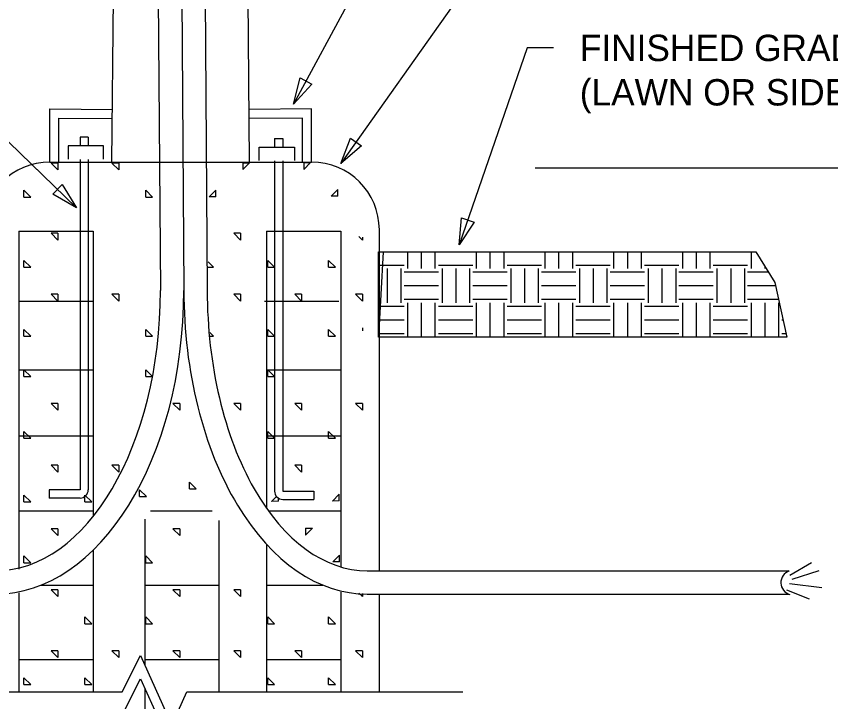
# Model space of a CAD drawing. Extents: x 10112 to 10168, y 10050 to 10179.
# Drawn here: x 10136.31 to 10156.9, y 10084.18 to 10101.49 of the extents above; entities that cross this region are included whole.
import ezdxf

# ---------------------------------------------------------------- set-up
doc = ezdxf.new("R2010")
doc.units = 0
for name, color, linetype in [('G-ANNO-TEXT', 7, 'Continuous'), ('G-DETL-LINE', 7, 'Continuous'), ('G-DETL-OTLN', 7, 'Continuous'), ('G-DETL-PATT', 7, 'Continuous')]:
    doc.layers.add(name, color=color, linetype=linetype)

msp = doc.modelspace()

# ---------------------------------------------------------------- linework, layer by layer
at = {"layer": 'G-ANNO-TEXT'}
for p, q in [((10148.104, 10108.141), (10143.31, 10099.275)), ((10129.887, 10104.328), (10137.827, 10096.658)), ((10148.282, 10103.102), (10144.508, 10097.776)), ((10149.219, 10100.696), (10147.504, 10095.721)), ((10149.886, 10100.696), (10149.219, 10100.696)), ((10149.421, 10097.663), (10167.894, 10097.663))]:
    msp.add_line(p, q, dxfattribs=at)
for points in [[(10143.774, 10099.782), (10143.31, 10099.275), (10143.48, 10099.941)], [(10145.03, 10098.224), (10144.508, 10097.776), (10144.758, 10098.417)], [(10137.464, 10097.241), (10137.827, 10096.658), (10137.232, 10097.001)], [(10147.879, 10096.297), (10147.504, 10095.721), (10147.564, 10096.406)]]:
    msp.add_lwpolyline(points, close=True, dxfattribs=at)
at = {"layer": 'G-DETL-LINE'}
for p, q in [((10137.384, 10097.812), (10137.384, 10098.923)), ((10137.384, 10098.923), (10138.734, 10098.916)), ((10143.545, 10098.923), (10142.195, 10098.916)), ((10143.545, 10097.812), (10143.545, 10098.923)), ((10137.916, 10098.443), (10137.916, 10098.219)), ((10138.124, 10098.443), (10137.916, 10098.443)), ((10138.124, 10098.443), (10138.124, 10098.219)), ((10142.835, 10098.408), (10143.043, 10098.408)), ((10142.835, 10098.408), (10142.835, 10098.185)), ((10143.043, 10098.408), (10143.043, 10098.185)), ((10138.512, 10098.219), (10137.617, 10098.219)), ((10137.617, 10098.219), (10137.617, 10097.883)), ((10138.512, 10097.883), (10138.512, 10098.219)), ((10142.447, 10098.185), (10143.341, 10098.185)), ((10142.447, 10097.849), (10142.447, 10098.185)), ((10143.341, 10098.185), (10143.341, 10097.849)), ((10137.916, 10097.88), (10137.916, 10089.532)), ((10138.124, 10097.88), (10138.124, 10089.532)), ((10142.835, 10097.846), (10142.835, 10089.498)), ((10143.043, 10097.846), (10143.043, 10089.498)), ((10136.367, 10096.069), (10138.245, 10096.069)), ((10136.367, 10096.069), (10136.367, 10087.528)), ((10138.245, 10096.069), (10138.245, 10088.854)), ((10142.634, 10096.069), (10144.511, 10096.069)), ((10142.634, 10096.069), (10142.634, 10089.061)), ((10144.511, 10096.069), (10144.511, 10087.582)), ((10145.584, 10095.546), (10145.464, 10093.385)), ((10145.584, 10095.546), (10155.003, 10095.546)), ((10155.003, 10095.546), (10155.483, 10094.765)), ((10155.483, 10094.765), (10155.783, 10093.385)), ((10136.367, 10094.294), (10138.245, 10094.294)), ((10142.584, 10094.294), (10144.462, 10094.294)), ((10155.783, 10093.385), (10145.464, 10093.385)), ((10136.367, 10092.562), (10138.245, 10092.562)), ((10142.634, 10092.562), (10144.511, 10092.562)), ((10136.367, 10090.891), (10138.245, 10090.891)), ((10142.634, 10090.891), (10144.511, 10090.891)), ((10137.916, 10089.532), (10137.133, 10089.532)), ((10137.133, 10089.532), (10137.133, 10089.323)), ((10143.043, 10089.498), (10143.826, 10089.498)), ((10143.826, 10089.498), (10143.826, 10089.289)), ((10137.916, 10089.323), (10137.133, 10089.323)), ((10143.043, 10089.289), (10143.826, 10089.289)), ((10136.367, 10089), (10138.245, 10089)), ((10139.7, 10089), (10141.26, 10089)), ((10142.677, 10089), (10144.511, 10089)), ((10139.553, 10088.79), (10139.553, 10085.113)), ((10141.43, 10088.759), (10141.43, 10084.43)), ((10142.634, 10088.152), (10142.634, 10084.43)), ((10138.245, 10088.001), (10138.245, 10084.43)), ((10136.934, 10087.122), (10138.245, 10087.122)), ((10139.553, 10087.122), (10141.43, 10087.122)), ((10142.634, 10087.122), (10144.056, 10087.122)), ((10136.367, 10086.931), (10136.367, 10084.43)), ((10144.511, 10086.942), (10144.511, 10084.43)), ((10136.367, 10085.244), (10138.245, 10085.244)), ((10139.553, 10085.244), (10141.43, 10085.244)), ((10142.634, 10085.244), (10144.511, 10085.244)), ((10139.553, 10084.522), (10139.553, 10081.489))]:
    msp.add_line(p, q, dxfattribs=at)
for centre, start, end in [((10137.916, 10089.532), 270, 0), ((10143.043, 10089.498), 180, 270)]:
    msp.add_arc(centre, 0.209, start, end, dxfattribs=at)
at = {"layer": 'G-DETL-OTLN'}
for p, q in [((10138.725, 10097.812), (10138.896, 10117.867)), ((10142.204, 10097.812), (10142.103, 10109.706)), ((10140.48, 10103.946), (10140.541, 10094.563)), ((10141.072, 10103.946), (10141.132, 10094.563)), ((10139.889, 10102.53), (10139.949, 10094.563)), ((10137.156, 10099.153), (10138.736, 10099.144)), ((10137.156, 10097.812), (10137.156, 10099.153)), ((10143.773, 10099.153), (10142.193, 10099.144)), ((10143.773, 10097.812), (10143.773, 10099.153)), ((10137.156, 10097.812), (10143.773, 10097.812)), ((10145.484, 10087.486), (10145.484, 10096.101)), ((10155.866, 10087.373), (10156.414, 10087.692)), ((10145.179, 10087.486), (10155.848, 10087.486)), ((10155.925, 10087.273), (10156.604, 10087.493)), ((10155.856, 10087.163), (10156.673, 10087.063)), ((10145.179, 10086.894), (10155.848, 10086.894)), ((10145.484, 10084.43), (10145.484, 10086.894)), ((10155.776, 10087.004), (10156.354, 10086.774))]:
    msp.add_line(p, q, dxfattribs=at)
for centre, radius, start, end in [((10137.156, 10096.101), 1.711, 90, 180), ((10143.773, 10096.101), 1.711, 360, 90), ((10155.95, 10087.186), 0.314, 109.387, 254.428)]:
    msp.add_arc(centre, radius, start, end, dxfattribs=at)
for centre, major_axis, ratio, start_param, end_param in [((10135.782, 10094.563), (0, 7.669), 0.620486, 3.141593, 4.712389), ((10135.782, 10094.563), (0, 7.078), 0.588771, 3.141593, 4.712389), ((10145.179, 10094.563), (0, 7.669), 0.604733, 1.570796, 3.141593), ((10145.179, 10094.563), (0, 7.078), 0.571702, 1.570796, 3.141593)]:
    msp.add_ellipse(centre, major_axis=major_axis, ratio=ratio, start_param=start_param, end_param=end_param, dxfattribs=at)
at = {"layer": 'G-DETL-PATT'}
for p, q in [((10137.356, 10097.784), (10137.185, 10097.784)), ((10137.356, 10097.613), (10137.185, 10097.784)), ((10137.356, 10097.784), (10137.356, 10097.613)), ((10138.896, 10097.784), (10138.725, 10097.784)), ((10138.896, 10097.613), (10138.725, 10097.784)), ((10138.896, 10097.784), (10138.896, 10097.613)), ((10142.033, 10097.792), (10142.204, 10097.793)), ((10142.033, 10097.792), (10142.034, 10097.621)), ((10142.034, 10097.621), (10142.204, 10097.793)), ((10143.573, 10097.8), (10143.744, 10097.8)), ((10143.573, 10097.8), (10143.574, 10097.628)), ((10143.574, 10097.628), (10143.745, 10097.8)), ((10143.715, 10097.74), (10143.715, 10097.74)), ((10136.5, 10096.928), (10136.5, 10097.099)), ((10136.671, 10096.928), (10136.5, 10097.099)), ((10139.58, 10096.928), (10139.58, 10097.099)), ((10139.752, 10096.928), (10139.58, 10097.099)), ((10139.604, 10097.087), (10139.604, 10097.087)), ((10141.182, 10096.932), (10141.352, 10097.104)), ((10141.329, 10097.091), (10141.329, 10097.091)), ((10141.353, 10096.933), (10141.352, 10097.104)), ((10144.262, 10096.947), (10144.432, 10097.119)), ((10144.433, 10096.948), (10144.432, 10097.119)), ((10136.5, 10096.928), (10136.672, 10096.928)), ((10139.58, 10096.928), (10139.752, 10096.928)), ((10141.353, 10096.933), (10141.182, 10096.932)), ((10144.433, 10096.948), (10144.262, 10096.947)), ((10137.356, 10096.012), (10137.185, 10096.012)), ((10137.356, 10095.841), (10137.185, 10096.012)), ((10137.356, 10096.012), (10137.356, 10095.841)), ((10141.976, 10096.012), (10141.805, 10096.012)), ((10141.976, 10095.841), (10141.805, 10096.012)), ((10141.976, 10096.012), (10141.976, 10095.841)), ((10145.056, 10095.841), (10144.969, 10095.928)), ((10145.031, 10095.847), (10145.031, 10095.847)), ((10145.056, 10095.917), (10145.056, 10095.841)), ((10146.195, 10095.546), (10146.195, 10095.121)), ((10146.543, 10095.546), (10146.543, 10095.121)), ((10146.89, 10095.546), (10146.89, 10095.121)), ((10147.933, 10095.546), (10147.933, 10095.121)), ((10148.28, 10095.546), (10148.28, 10095.121)), ((10148.628, 10095.546), (10148.628, 10095.121)), ((10149.67, 10095.546), (10149.67, 10095.121)), ((10150.017, 10095.546), (10150.017, 10095.121)), ((10150.365, 10095.546), (10150.365, 10095.121)), ((10151.407, 10095.546), (10151.407, 10095.121)), ((10151.755, 10095.546), (10151.755, 10095.121)), ((10152.102, 10095.546), (10152.102, 10095.121)), ((10153.145, 10095.546), (10153.145, 10095.121)), ((10153.492, 10095.546), (10153.492, 10095.121)), ((10153.84, 10095.546), (10153.84, 10095.121)), ((10154.882, 10095.546), (10154.882, 10095.121)), ((10136.5, 10095.157), (10136.5, 10095.328)), ((10136.671, 10095.157), (10136.5, 10095.328)), ((10142.661, 10095.157), (10142.661, 10095.328)), ((10142.832, 10095.157), (10142.661, 10095.328)), ((10144.201, 10095.157), (10144.201, 10095.328)), ((10144.372, 10095.157), (10144.201, 10095.328)), ((10136.5, 10095.157), (10136.672, 10095.157)), ((10141.292, 10095.157), (10141.155, 10095.294)), ((10141.155, 10095.157), (10141.292, 10095.157)), ((10142.661, 10095.157), (10142.832, 10095.157)), ((10144.201, 10095.157), (10144.372, 10095.157)), ((10145.464, 10095.208), (10146.109, 10095.208)), ((10145.681, 10095.121), (10145.681, 10094.253)), ((10146.028, 10095.121), (10146.028, 10094.253)), ((10146.977, 10095.208), (10147.846, 10095.208)), ((10147.07, 10095.121), (10147.07, 10094.253)), ((10147.418, 10095.121), (10147.418, 10094.253)), ((10147.765, 10095.121), (10147.765, 10094.253)), ((10148.714, 10095.208), (10149.583, 10095.208)), ((10148.808, 10095.121), (10148.808, 10094.253)), ((10149.155, 10095.121), (10149.155, 10094.253)), ((10149.503, 10095.121), (10149.503, 10094.253)), ((10150.452, 10095.208), (10151.32, 10095.208)), ((10150.545, 10095.121), (10150.545, 10094.253)), ((10150.893, 10095.121), (10150.893, 10094.253)), ((10151.24, 10095.121), (10151.24, 10094.253)), ((10152.189, 10095.208), (10153.058, 10095.208)), ((10152.282, 10095.121), (10152.282, 10094.253)), ((10152.63, 10095.121), (10152.63, 10094.253)), ((10152.977, 10095.121), (10152.977, 10094.253)), ((10153.926, 10095.208), (10154.795, 10095.208)), ((10154.02, 10095.121), (10154.02, 10094.253)), ((10154.367, 10095.121), (10154.367, 10094.253)), ((10154.715, 10095.121), (10154.715, 10094.253)), ((10155.229, 10095.177), (10155.229, 10095.121)), ((10146.109, 10095.04), (10146.977, 10095.04)), ((10147.846, 10095.04), (10148.714, 10095.04)), ((10149.583, 10095.04), (10150.452, 10095.04)), ((10151.32, 10095.04), (10152.189, 10095.04)), ((10153.058, 10095.04), (10153.926, 10095.04)), ((10154.795, 10095.04), (10155.314, 10095.04)), ((10146.109, 10094.693), (10146.977, 10094.693)), ((10147.846, 10094.693), (10148.714, 10094.693)), ((10149.583, 10094.693), (10150.452, 10094.693)), ((10151.32, 10094.693), (10152.189, 10094.693)), ((10153.058, 10094.693), (10153.926, 10094.693)), ((10154.795, 10094.693), (10155.499, 10094.693)), ((10137.356, 10094.472), (10137.185, 10094.472)), ((10137.356, 10094.301), (10137.185, 10094.472)), ((10137.356, 10094.472), (10137.356, 10094.301)), ((10138.896, 10094.472), (10138.725, 10094.472)), ((10138.896, 10094.301), (10138.725, 10094.472)), ((10138.896, 10094.472), (10138.896, 10094.301)), ((10141.976, 10094.472), (10141.805, 10094.472)), ((10141.976, 10094.301), (10141.805, 10094.472)), ((10141.976, 10094.472), (10141.976, 10094.301)), ((10143.516, 10094.472), (10143.345, 10094.472)), ((10143.516, 10094.301), (10143.345, 10094.472)), ((10143.515, 10094.35), (10143.515, 10094.35)), ((10143.516, 10094.472), (10143.516, 10094.301)), ((10145.056, 10094.472), (10144.885, 10094.472)), ((10145.056, 10094.301), (10144.885, 10094.472)), ((10145.056, 10094.472), (10145.056, 10094.301)), ((10146.109, 10094.345), (10146.977, 10094.345)), ((10147.846, 10094.345), (10148.714, 10094.345)), ((10149.583, 10094.345), (10150.452, 10094.345)), ((10151.32, 10094.345), (10152.189, 10094.345)), ((10153.058, 10094.345), (10153.926, 10094.345)), ((10154.795, 10094.345), (10155.574, 10094.345)), ((10145.464, 10094.172), (10146.109, 10094.172)), ((10146.195, 10094.259), (10146.195, 10093.39)), ((10146.543, 10094.259), (10146.543, 10093.39)), ((10146.89, 10094.259), (10146.89, 10093.39)), ((10146.977, 10094.172), (10147.846, 10094.172)), ((10147.933, 10094.259), (10147.933, 10093.39)), ((10148.28, 10094.259), (10148.28, 10093.39)), ((10148.628, 10094.259), (10148.628, 10093.39)), ((10148.714, 10094.172), (10149.583, 10094.172)), ((10149.67, 10094.259), (10149.67, 10093.39)), ((10150.017, 10094.259), (10150.017, 10093.39)), ((10150.365, 10094.259), (10150.365, 10093.39)), ((10150.452, 10094.172), (10151.32, 10094.172)), ((10151.407, 10094.259), (10151.407, 10093.39)), ((10151.755, 10094.259), (10151.755, 10093.39)), ((10152.102, 10094.259), (10152.102, 10093.39)), ((10152.189, 10094.172), (10153.058, 10094.172)), ((10153.145, 10094.259), (10153.145, 10093.39)), ((10153.492, 10094.259), (10153.492, 10093.39)), ((10153.84, 10094.259), (10153.84, 10093.39)), ((10153.926, 10094.172), (10154.795, 10094.172)), ((10154.882, 10094.259), (10154.882, 10093.39)), ((10155.229, 10094.259), (10155.229, 10093.39)), ((10155.577, 10094.259), (10155.577, 10093.39)), ((10145.464, 10093.824), (10146.109, 10093.824)), ((10146.977, 10093.824), (10147.846, 10093.824)), ((10148.714, 10093.824), (10149.583, 10093.824)), ((10150.452, 10093.824), (10151.32, 10093.824)), ((10152.189, 10093.824), (10153.058, 10093.824)), ((10153.926, 10093.824), (10154.795, 10093.824)), ((10155.664, 10093.824), (10155.687, 10093.824)), ((10136.5, 10093.409), (10136.5, 10093.58)), ((10136.671, 10093.409), (10136.5, 10093.58)), ((10139.58, 10093.409), (10139.58, 10093.58)), ((10139.752, 10093.409), (10139.58, 10093.58)), ((10141.292, 10093.409), (10141.196, 10093.504)), ((10142.661, 10093.409), (10142.661, 10093.58)), ((10142.832, 10093.409), (10142.661, 10093.58)), ((10144.201, 10093.409), (10144.201, 10093.58)), ((10144.372, 10093.409), (10144.201, 10093.58)), ((10145.056, 10093.622), (10145.056, 10093.545)), ((10145.464, 10093.477), (10146.109, 10093.477)), ((10146.977, 10093.477), (10147.846, 10093.477)), ((10148.714, 10093.477), (10149.583, 10093.477)), ((10150.452, 10093.477), (10151.32, 10093.477)), ((10152.189, 10093.477), (10153.058, 10093.477)), ((10153.926, 10093.477), (10154.795, 10093.477)), ((10155.664, 10093.477), (10155.763, 10093.477)), ((10136.5, 10093.409), (10136.672, 10093.409)), ((10139.58, 10093.409), (10139.752, 10093.409)), ((10141.204, 10093.409), (10141.292, 10093.409)), ((10142.661, 10093.409), (10142.832, 10093.409)), ((10144.201, 10093.409), (10144.372, 10093.409)), ((10145.681, 10093.39), (10145.681, 10093.385)), ((10146.028, 10093.39), (10146.028, 10093.385)), ((10147.07, 10093.39), (10147.07, 10093.385)), ((10147.418, 10093.39), (10147.418, 10093.385)), ((10147.765, 10093.39), (10147.765, 10093.385)), ((10148.808, 10093.39), (10148.808, 10093.385)), ((10149.155, 10093.39), (10149.155, 10093.385)), ((10149.503, 10093.39), (10149.503, 10093.385)), ((10150.545, 10093.39), (10150.545, 10093.385)), ((10150.893, 10093.39), (10150.893, 10093.385)), ((10151.24, 10093.39), (10151.24, 10093.385)), ((10152.282, 10093.39), (10152.282, 10093.385)), ((10152.63, 10093.39), (10152.63, 10093.385)), ((10152.977, 10093.39), (10152.977, 10093.385)), ((10154.02, 10093.39), (10154.02, 10093.385)), ((10154.367, 10093.39), (10154.367, 10093.385)), ((10154.715, 10093.39), (10154.715, 10093.385)), ((10155.757, 10093.39), (10155.757, 10093.385)), ((10136.5, 10092.395), (10136.5, 10092.566)), ((10136.671, 10092.395), (10136.5, 10092.566)), ((10139.58, 10092.395), (10139.58, 10092.566)), ((10139.752, 10092.395), (10139.58, 10092.566)), ((10142.661, 10092.395), (10142.661, 10092.566)), ((10142.832, 10092.395), (10142.661, 10092.566)), ((10142.665, 10092.559), (10142.665, 10092.559)), ((10136.5, 10092.395), (10136.672, 10092.395)), ((10139.58, 10092.395), (10139.752, 10092.395)), ((10142.661, 10092.395), (10142.832, 10092.395)), ((10137.356, 10091.711), (10137.185, 10091.711)), ((10137.356, 10091.539), (10137.185, 10091.711)), ((10137.356, 10091.711), (10137.356, 10091.539)), ((10140.436, 10091.711), (10140.265, 10091.711)), ((10140.436, 10091.539), (10140.265, 10091.711)), ((10140.436, 10091.711), (10140.436, 10091.539)), ((10141.976, 10091.711), (10141.805, 10091.711)), ((10141.976, 10091.539), (10141.805, 10091.711)), ((10141.976, 10091.711), (10141.976, 10091.539)), ((10143.516, 10091.711), (10143.345, 10091.711)), ((10143.516, 10091.539), (10143.345, 10091.711)), ((10143.516, 10091.711), (10143.516, 10091.539)), ((10145.056, 10091.711), (10144.885, 10091.711)), ((10145.056, 10091.539), (10144.885, 10091.711)), ((10145.056, 10091.711), (10145.056, 10091.539)), ((10137.253, 10091.587), (10137.253, 10091.587)), ((10143.515, 10091.589), (10143.515, 10091.589)), ((10136.5, 10090.833), (10136.5, 10091.004)), ((10136.671, 10090.833), (10136.5, 10091.004)), ((10142.661, 10090.833), (10142.661, 10091.004)), ((10142.832, 10090.833), (10142.661, 10091.004)), ((10144.201, 10090.833), (10144.201, 10091.004)), ((10144.372, 10090.833), (10144.201, 10091.004)), ((10136.5, 10090.833), (10136.672, 10090.833)), ((10142.661, 10090.833), (10142.832, 10090.833)), ((10144.201, 10090.833), (10144.372, 10090.833)), ((10137.356, 10090.149), (10137.185, 10090.149)), ((10137.356, 10089.978), (10137.185, 10090.149)), ((10137.253, 10090.025), (10137.253, 10090.025)), ((10137.356, 10090.149), (10137.356, 10089.978)), ((10138.896, 10090.149), (10138.725, 10090.149)), ((10138.896, 10089.978), (10138.725, 10090.149)), ((10138.896, 10090.149), (10138.896, 10089.978)), ((10143.516, 10090.149), (10143.345, 10090.149)), ((10143.516, 10089.978), (10143.345, 10090.149)), ((10143.515, 10090.027), (10143.515, 10090.027)), ((10143.516, 10090.149), (10143.516, 10089.978)), ((10140.854, 10089.551), (10140.682, 10089.722)), ((10140.683, 10089.551), (10140.683, 10089.722)), ((10140.683, 10089.551), (10140.854, 10089.551)), ((10136.5, 10089.228), (10136.5, 10089.399)), ((10136.671, 10089.228), (10136.5, 10089.399)), ((10138.04, 10089.228), (10138.04, 10089.399)), ((10138.212, 10089.228), (10138.04, 10089.399)), ((10139.395, 10089.493), (10139.395, 10089.493)), ((10139.423, 10089.359), (10139.423, 10089.53)), ((10139.594, 10089.359), (10139.423, 10089.53)), ((10139.423, 10089.359), (10139.594, 10089.359)), ((10142.761, 10089.239), (10142.884, 10089.363)), ((10144.301, 10089.247), (10144.471, 10089.419)), ((10144.472, 10089.248), (10144.471, 10089.419)), ((10136.5, 10089.228), (10136.672, 10089.228)), ((10138.04, 10089.228), (10138.212, 10089.228)), ((10142.932, 10089.24), (10142.761, 10089.239)), ((10142.932, 10089.24), (10142.932, 10089.322)), ((10144.472, 10089.248), (10144.301, 10089.247)), ((10137.356, 10088.544), (10137.185, 10088.544)), ((10137.356, 10088.372), (10137.185, 10088.543)), ((10137.356, 10088.544), (10137.356, 10088.372)), ((10140.436, 10088.544), (10140.265, 10088.544)), ((10140.436, 10088.372), (10140.265, 10088.543)), ((10140.436, 10088.544), (10140.436, 10088.372)), ((10143.62, 10088.559), (10143.791, 10088.56)), ((10143.62, 10088.559), (10143.621, 10088.388)), ((10143.621, 10088.388), (10143.791, 10088.56)), ((10136.5, 10087.688), (10136.5, 10087.859)), ((10136.671, 10087.688), (10136.5, 10087.859)), ((10136.5, 10087.688), (10136.672, 10087.688)), ((10139.58, 10087.688), (10139.58, 10087.859)), ((10139.752, 10087.688), (10139.58, 10087.859)), ((10139.58, 10087.688), (10139.752, 10087.688)), ((10144.309, 10087.707), (10144.479, 10087.879)), ((10144.48, 10087.708), (10144.309, 10087.707)), ((10144.48, 10087.708), (10144.479, 10087.879)), ((10137.356, 10087.003), (10137.185, 10087.003)), ((10137.356, 10086.832), (10137.185, 10087.003)), ((10137.356, 10087.003), (10137.356, 10086.832)), ((10140.436, 10087.003), (10140.265, 10087.003)), ((10140.436, 10086.832), (10140.265, 10087.003)), ((10140.436, 10087.003), (10140.436, 10086.832)), ((10141.976, 10087.003), (10141.805, 10087.003)), ((10141.976, 10086.832), (10141.805, 10087.003)), ((10141.976, 10087.003), (10141.976, 10086.832)), ((10145.056, 10086.832), (10144.969, 10086.919)), ((10145.056, 10086.909), (10145.056, 10086.832)), ((10145.031, 10086.838), (10145.031, 10086.838)), ((10138.04, 10086.148), (10138.04, 10086.319)), ((10138.212, 10086.148), (10138.04, 10086.319)), ((10139.58, 10086.148), (10139.58, 10086.319)), ((10139.752, 10086.148), (10139.58, 10086.319)), ((10142.661, 10086.148), (10142.661, 10086.319)), ((10142.832, 10086.148), (10142.661, 10086.319)), ((10144.201, 10086.148), (10144.201, 10086.319)), ((10144.372, 10086.148), (10144.201, 10086.319)), ((10138.04, 10086.148), (10138.212, 10086.148)), ((10139.58, 10086.148), (10139.752, 10086.148)), ((10142.661, 10086.148), (10142.832, 10086.148)), ((10144.201, 10086.148), (10144.372, 10086.148)), ((10137.356, 10085.463), (10137.185, 10085.463)), ((10137.356, 10085.292), (10137.185, 10085.463)), ((10137.356, 10085.463), (10137.356, 10085.292)), ((10138.896, 10085.463), (10138.725, 10085.463)), ((10138.896, 10085.292), (10138.725, 10085.463)), ((10138.896, 10085.463), (10138.896, 10085.292)), ((10140.436, 10085.463), (10140.265, 10085.463)), ((10140.436, 10085.292), (10140.265, 10085.463)), ((10140.436, 10085.463), (10140.436, 10085.292)), ((10141.976, 10085.463), (10141.805, 10085.463)), ((10141.976, 10085.292), (10141.805, 10085.463)), ((10141.976, 10085.463), (10141.976, 10085.292)), ((10143.516, 10085.463), (10143.345, 10085.463)), ((10143.516, 10085.292), (10143.345, 10085.463)), ((10143.516, 10085.463), (10143.516, 10085.292)), ((10145.056, 10085.463), (10144.885, 10085.463)), ((10145.056, 10085.292), (10144.885, 10085.463)), ((10145.056, 10085.463), (10145.056, 10085.292)), ((10138.985, 10084.43), (10139.447, 10085.348)), ((10139.447, 10085.348), (10140.24, 10083.58)), ((10143.515, 10085.341), (10143.515, 10085.341)), ((10136.5, 10084.608), (10136.5, 10084.779)), ((10136.671, 10084.608), (10136.5, 10084.779)), ((10136.5, 10084.608), (10136.672, 10084.608)), ((10138.04, 10084.608), (10138.04, 10084.779)), ((10138.212, 10084.608), (10138.04, 10084.779)), ((10138.04, 10084.608), (10138.212, 10084.608)), ((10138.985, 10083.838), (10139.447, 10084.757)), ((10139.447, 10084.757), (10140.24, 10082.989)), ((10142.661, 10084.608), (10142.661, 10084.779)), ((10142.832, 10084.608), (10142.661, 10084.779)), ((10142.661, 10084.608), (10142.832, 10084.608)), ((10144.201, 10084.608), (10144.201, 10084.779)), ((10144.372, 10084.608), (10144.201, 10084.779)), ((10144.201, 10084.608), (10144.372, 10084.608)), ((10132.608, 10084.43), (10138.985, 10084.43)), ((10140.24, 10083.58), (10140.62, 10084.43)), ((10140.62, 10084.43), (10147.596, 10084.43))]:
    msp.add_line(p, q, dxfattribs=at)
msp.add_lwpolyline([(10145.584, 10095.546), (10155.003, 10095.546), (10155.483, 10094.765), (10155.783, 10093.385), (10145.464, 10093.385), (10145.464, 10095.546)], close=True, dxfattribs=at)

# ---------------------------------------------------------------- texts
at = {"layer": 'G-ANNO-TEXT'}
for s, p in [('FINISHED GRADE', (10150.552, 10100.363)), ('(LAWN OR SIDEWALK)', (10150.552, 10099.241))]:
    msp.add_text(s, height=0.66667, dxfattribs=at).set_placement(p)

doc.saveas('drawing.dxf')
